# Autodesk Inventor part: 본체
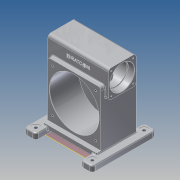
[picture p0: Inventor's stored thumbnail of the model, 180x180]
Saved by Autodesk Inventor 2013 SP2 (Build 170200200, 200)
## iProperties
Created: 2025-06
Part Number: 본체
Material: 알루미늄 6061
Document SubType Name: Modeling
Designer: i
Density: 2.71 g/cm^3
Mass: 8033.67 g
Surface Area: 3449.31 cm^2
Volume: 2964.45 cm^3
Author: i
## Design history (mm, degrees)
sketch "스케치1"
  geometry: L1 (-38, 48)-(38, 48); L2 (48, 38)-(48, -38); L3 (38, -48)-(-38, -48); L4 (-48, -38)-(-48, 38); L5 (-48, 48)-(48, -48); L6 (48, 48)-(-48, -48); C1 r 38.5 at (0, 0); A1 r 10 centre (38, 38) between (48, 38) and (38, 48); A2 r 10 centre (-38, 38) between (-38, 48) and (-48, 38); A3 r 10 centre (-38, -38) between (-48, -38) and (-38, -48); A4 r 10 centre (38, -38) between (38, -48) and (48, -38); 1 further point
  constraints: 12 end point, 8 point on circle, 8 point on line, 8 tangent, 5 centre point, 3 equal radius, 2 midpoint, 2 parallel, 1 coincident, 1 horizontal, 1 perpendicular
  dimensions: "d0" = 96 distance between parallel lines of L4 L2; "d2" = 96 distance between parallel lines of L3 L1; "d3" = 77 diameter of C1; "d6" = 10 radius of A1
extrude "돌출1" new body sketch "스케치1" stored distance "d4" = 210; taper "d5" = 0 deg
sketch "스케치2"
  geometry: L1 (-213, 77)-(-7, 77); L2 (-7, 77)-(-7, -63); L3 (-7, -63)-(-213, -63); L4 (-213, -63)-(-213, 77); L5 (-213, 77)-(-7, -63); L6 (-7, 77)-(-213, -63); L7 (-38, -48)-(38, -48) reference; L8 (48, -38)-(48, 38) reference; 2 further points
  constraints: 12 end point, 2 midpoint, 2 parallel, 1 horizontal, 1 perpendicular
  dimensions: "d9" = 15 distance between parallel lines of L3 L7; "d10" = 206 distance between parallel lines of L4 L2; "d11" = 140 distance between parallel lines of L3 L1; "d12" = 261 distance between parallel lines of L4 L8
extrude "돌출2" join sketch "스케치2" stored distance "d13" = 186; taper "d14" = 0 deg
fillet "모깎기1" dims "d15" = 10
node "작업 평면1"
sketch "스케치3"
  geometry: L1 (171, 180)-(191, 180); L2 (201, 170)-(201, -30); L3 (191, -40)-(171, -40); L4 (161, -30)-(161, 170); L5 (161, 180)-(201, -40); L6 (201, 180)-(161, -40); L7 (176, 0)-(176, 140) reference; A1 r 10 centre (171, 170) between (171, 180) and (161, 170); A2 r 10 centre (191, 170) between (201, 170) and (191, 180); A3 r 10 centre (171, -30) between (161, -30) and (171, -40); A4 r 10 centre (191, -30) between (191, -40) and (201, -30); 4 further points
  constraints: 12 end point, 8 point on circle, 8 point on line, 8 tangent, 4 centre point, 4 midpoint, 3 equal radius, 2 parallel, 1 horizontal, 1 horizontal alignment, 1 perpendicular
  dimensions: "d17" = 220 distance between parallel lines of L1 L3; "d20" = 40 distance between parallel lines of L2 L4; "d21" = 10 radius of A1; "d130" = 118 distance from line of point (83, 63) L2
extrude "돌출3" join sketch "스케치3" distance "d22" = 20; taper "d23" = 0 deg
sketch "스케치4"
  geometry: L1 (176, -10)-(176, -196) reference; L2 (166, 0)-(0, 0) reference; L3 (-10, 0)-(176, 0); L4 (176, 0)-(176, -189); L5 (176, -189)-(-10, -189); L6 (-10, -189)-(-10, 0); 2 further points
  constraints: 8 end point, 2 midpoint, 2 parallel, 1 horizontal, 1 perpendicular, 1 point on line
  dimensions: "d24" = 189 distance between parallel lines of L5 L3
extrude "돌출4" cut sketch "스케치4" distance "d26" = 15; taper "d27" = 0 deg
node "작업 평면2"
sketch "스케치5"
  geometry: 1 further point
sketch "스케치6"
  geometry: L1 (63, -17)-(63, -203) reference; L2 (56, -83)-(56, -83); L3 (-62, -7)-(-48, -7) reference; L4 (-62, -100)-(59, -100); L5 (56, -70)-(56, -73); L6 (56, -73)-(56, -73); L7 (59, -76)-(59, -100); L8 (-62, -14)-(-62, -100); L9 (-62, -196)-(-62, -17) reference; L10 (-62, -14)-(40, -14); L11 (93, -223)-(-107, -223) reference; L12 (40, -14)-(40, -68); L13 (41, -69)-(55, -69); L14 (40, -68)-(41, -69); A1 r 1 centre (55, -70) between (56, -70) and (55, -69); A2 r 3 centre (56, -76) between (59, -76) and (56, -73); 2 further points
  constraints: 20 end point, 4 point on circle, 4 tangent, 3 perpendicular, 2 centre point, 2 parallel, 2 point on line, 1 vertical alignment
  dimensions: "d47" = 54 diameter of L6 L4; "d50" = 3 distance between parallel lines of L7 L5; "d53" = 1 radius of A1; "d54" = 3 radius of A2; "d55" = 172 diameter of L10 L4; "d60" = 100 vertical distance of L4.start point (0, 0); "d61" = 1 distance of L12.end point (40, -69); "d62" = 1 distance of L13.start point (40, -69) (= d61); "d63" = 16 distance between parallel lines of L5 L12
revolve "회전1" sketch "스케치6" stored, may be unused: angle "d64" = 90 deg
sketch "스케치7"
  geometry: L1 (-165.2, 0)-(165.2, 0) reference; L2 (82, 0)-(105, 0); L3 (105, 0)-(105, 42.5); L4 (105, 42.5)-(82, 42.5); L5 (82, 42.5)-(82, 0); L6 (105, 38.5)-(105, -38.5) reference; 2 further points
  constraints: 8 end point, 2 parallel, 1 coincident, 1 horizontal, 1 midpoint, 1 perpendicular, 1 point on line
  dimensions: "d66" = 85 diameter of L4 L1; "d67" = 23 distance between parallel lines of L3 L5
revolve "회전2" sketch "스케치7" stored, may be unused: angle "d68" = 90 deg
sketch "스케치8"
  geometry: C1 r 42.5 at (0, 0) reference; C2 r 38.5 at (0, 0)
  constraints: 1 centre point, 1 coincident
  dimensions: "d69" = 77 diameter of C2
extrude "돌출5" cut sketch "스케치8" stored distance "d70" = 15; taper "d71" = 0 deg
sketch "스케치9"
  geometry: A1 r 10 centre (-38, -38) between (-48, -38) and (-38, -48) reference; A2 r 10 centre (38, -38) between (38, -48) and (48, -38) reference; A3 r 10 centre (38, 38) between (48, 38) and (38, 48) reference; A4 r 10 centre (-38, 38) between (-38, 48) and (-48, 38) reference
hole "구멍5" sketch "스케치9" at (-38, 38), (-38, -38), (38, -38), (38, 38) diameter "d108" = 4.917; stored, may be unused: countersink angle "d112" = 90 deg, drill point angle "d114" = 118 deg; dims "d109" = 12, "d110" = 4, "d111" = 2, "d113" = 14
sketch "스케치10"
  geometry: L1 (158, -168)-(8, -168); L2 (8, -168)-(8, -18); L3 (8, -18)-(158, -18); L4 (158, -18)-(158, -168); L5 (158, -168)-(8, -18); L6 (8, -168)-(158, -18); C1 r 86 at (83, -93) reference; 1 further point
  constraints: 12 end point, 2 midpoint, 2 parallel, 1 horizontal, 1 perpendicular
  dimensions: "d115" = 150 distance of L2.end L3.end; "d116" = 150 distance between parallel lines of L1 L3
hole "구멍6" sketch "스케치10" at (8, -18), (158, -18), (158, -168), (8, -168) diameter "d117" = 6.647; stored, may be unused: countersink angle "d121" = 90 deg, drill point angle "d123" = 118 deg; dims "d118" = 16, "d119" = 4, "d120" = 2, "d122" = 18
sketch "스케치11"
  geometry: L1 (-10, -210)-(-10, -10) reference; L2 (186, -40)-(30, -40) reference; L3 (226, -210)-(226, -10) reference; L4 (10, -20)-(206, -20); L5 (206, -20)-(206, -200); L6 (206, -200)-(10, -200); L7 (10, -200)-(10, -20); 4 further points
  constraints: 8 end point, 3 midpoint, 2 parallel, 1 horizontal, 1 horizontal alignment, 1 perpendicular, 1 vertical alignment
  dimensions: "d127" = 180 distance between parallel lines of L6 L4; "d129" = 196 distance between parallel lines of L5 L7
hole "구멍7" sketch "스케치11" at (10, -20), (10, -200), (206, -200), (206, -20) diameter "d131" = 11; stored, may be unused: countersink angle "d135" = 82 deg, drill point angle "d137" = 0 deg; dims "d132" = 16, "d133" = 28, "d134" = 2, "d136" = 20
fillet "모깎기2" dims "d138" = 3
fillet "모깎기3" dims "d139" = 3
fillet "모깎기4" dims "d140" = 3
fillet "모깎기5" dims "d141" = 3
fillet "모깎기6" dims "d142" = 1.1
chamfer "모따기1" distance "d143" = 1; stored, may be unused: second distance "d144" = 2, angle "d145" = 45 deg
fillet "모깎기7" dims "d146" = 3
sketch "스케치12"
  geometry: L1 (0, 10)-(210, 10) reference; 3 further points
  constraints: 1 midpoint, 1 vertical alignment, 1 other
  dimensions: "d147" = 30 distance from line of point (105, -20) L1
feature "엠보싱1" sketch "스케치12" dims "d0" = 96, "d2" = 96, "d6" = 10, "d148" = 0.5, "d149" = 0
chamfer "모따기2" distance "d150" = 1; stored, may be unused: second distance "d151" = 2, angle "d152" = 45 deg
node "솔리드1"
mirror "대칭1"
mirror "대칭2"
mirror "대칭3"
